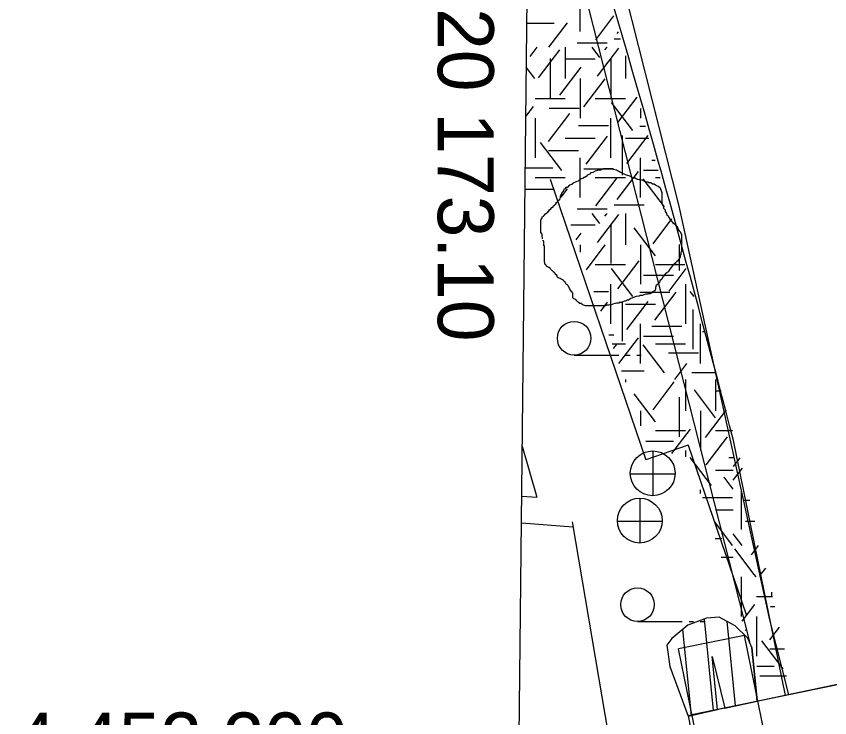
# Model space of a CAD drawing. Extents: x 419677 to 421689, y 4450851 to 4452923.
# Drawn here: x 420150.28 to 420186.6, y 4452201.02 to 4452232.31 of the extents above; entities that cross this region are included whole.
import ezdxf

# ---------------------------------------------------------------- set-up
doc = ezdxf.new("R2010")
doc.units = 0
for name, color, linetype in [('AA_HH', 7, 'Continuous'), ('Level 10', 7, 'Continuous'), ('Level 3', 7, 'Continuous'), ('Level 41', 7, 'Continuous'), ('Level 62', 7, 'Continuous')]:
    doc.layers.add(name, color=color, linetype=linetype)

msp = doc.modelspace()

# ---------------------------------------------------------------- linework, layer by layer
at = {"layer": 'AA_HH'}
for p, q in [((420175.184, 4452217.2), (420177.184, 4452217.2)), ((420177.484, 4452217.2), (420177.684, 4452217.2)), ((420177.984, 4452217.2), (420178.184, 4452217.2)), ((420178.707, 4452210.915), (420178.707, 4452212.915)), ((420177.687, 4452211.905), (420179.687, 4452211.905)), ((420178.13, 4452208.804), (420178.13, 4452210.804)), ((420177.11, 4452209.794), (420179.11, 4452209.794)), ((420178.014, 4452205.314), (420180.014, 4452205.314)), ((420180.314, 4452205.314), (420180.514, 4452205.314)), ((420180.814, 4452205.314), (420181.014, 4452205.314)), ((420180.988, 4452205.421), (420181.393, 4452201.335)), ((420182.003, 4452205.32), (420182.377, 4452201.544)), ((420180.029, 4452204.956), (420180.41, 4452201.119)), ((420183.124, 4452204.147), (420183.362, 4452201.75))]:
    msp.add_line(p, q, dxfattribs=at)
for points in [[(420173.096, 4452234.536), (420705.284, 4452228.915), (420698.004, 4451534.891), (420165.768, 4451540.511)], [(420183.362, 4452201.75), (420183.124, 4452204.147), (420182.934, 4452204.566), (420182.38, 4452205.123), (420181.654, 4452205.502), (420181.097, 4452205.463), (420180.263, 4452205.146), (420179.541, 4452204.558), (420179.324, 4452204.258), (420179.453, 4452203.306), (420180.281, 4452201.091), (420181.59, 4452201.378), (420181.351, 4452203.754), (420181.916, 4452201.447)]]:
    msp.add_lwpolyline(points, close=True, dxfattribs=at)
for points in [[(420174.846, 4452234.518), (420175.212, 4452233.92), (420175.779, 4452232.857), (420179.852, 4452216.802), (420183.01, 4452204.398)], [(420177.158, 4452234.493), (420179.853, 4452223.843), (420183.908, 4452205.378), (420184.76, 4452202.044)], [(420172.87, 4452213.132), (420173.523, 4452210.864)], [(420172.847, 4452210.9), (420173.523, 4452210.864)], [(420210.807, 4452207.509), (420180.279, 4452201.103), (420180.999, 4452197.376), (420210.769, 4452203.894)]]:
    msp.add_lwpolyline(points, dxfattribs=at)
for centre, radius in [((420175.184, 4452217.95), 0.75), ((420178.692, 4452211.923), 1), ((420178.115, 4452209.812), 1), ((420178.014, 4452206.064), 0.75)]:
    msp.add_circle(centre, radius, dxfattribs=at)
at = {"layer": 'Level 10'}
msp.add_line((420172.834, 4452209.708), (420175.136, 4452209.537), dxfattribs=at)
msp.add_lwpolyline([(420175.098, 4452209.758), (420183.741, 4452158.794), (420177.416, 4452142.041), (420172.015, 4452132.085)], dxfattribs=at)
at = {"layer": 'Level 3'}
for points in [[(420176.034, 4452225.364), (420176.138, 4452225.416), (420176.241, 4452225.442), (420176.241, 4452225.468), (420176.267, 4452225.468), (420176.293, 4452225.468), (420176.371, 4452225.468), (420176.501, 4452225.52), (420176.605, 4452225.52), (420176.682, 4452225.52), (420176.734, 4452225.52), (420176.812, 4452225.52), (420176.864, 4452225.52), (420176.89, 4452225.52), (420176.942, 4452225.494), (420177.072, 4452225.468), (420177.253, 4452225.364), (420177.461, 4452225.26), (420177.694, 4452225.182), (420177.772, 4452225.13), (420177.85, 4452225.104), (420177.902, 4452225.104), (420177.954, 4452225.078), (420178.005, 4452225.052), (420178.031, 4452225.052), (420178.083, 4452225.026), (420178.135, 4452225.026), (420178.239, 4452225), (420178.343, 4452224.948), (420178.42, 4452224.922), (420178.472, 4452224.922), (420178.524, 4452224.896), (420178.576, 4452224.896), (420178.602, 4452224.896), (420178.68, 4452224.845), (420178.758, 4452224.845), (420178.81, 4452224.793), (420178.861, 4452224.767), (420178.939, 4452224.741), (420178.991, 4452224.689), (420179.017, 4452224.689), (420179.043, 4452224.611), (420179.043, 4452224.585), (420179.069, 4452224.533), (420179.095, 4452224.455), (420179.095, 4452224.429), (420179.095, 4452224.351), (420179.095, 4452224.299), (420179.095, 4452224.221), (420179.095, 4452224.195), (420179.095, 4452224.117), (420179.095, 4452224.04), (420179.121, 4452223.91), (420179.173, 4452223.832), (420179.173, 4452223.754), (420179.251, 4452223.676), (420179.251, 4452223.598), (420179.302, 4452223.52), (420179.328, 4452223.442), (420179.38, 4452223.416), (420179.406, 4452223.338), (420179.458, 4452223.26), (420179.51, 4452223.183), (420179.588, 4452223.105), (420179.666, 4452223.053), (420179.717, 4452223.001), (420179.743, 4452222.975), (420179.795, 4452222.923), (420179.821, 4452222.819), (420179.873, 4452222.741), (420179.925, 4452222.715), (420179.951, 4452222.637), (420179.951, 4452222.611), (420179.977, 4452222.611), (420179.977, 4452222.585), (420179.977, 4452222.559), (420179.977, 4452222.507), (420179.977, 4452222.404), (420179.977, 4452222.352), (420179.977, 4452222.274), (420179.977, 4452222.196), (420179.977, 4452222.118), (420179.977, 4452222.04), (420179.977, 4452221.962), (420179.977, 4452221.91), (420179.977, 4452221.832), (420179.951, 4452221.78), (420179.951, 4452221.676), (420179.925, 4452221.65), (420179.925, 4452221.573), (420179.899, 4452221.547), (420179.899, 4452221.521), (420179.847, 4452221.469), (420179.795, 4452221.391), (420179.769, 4452221.391), (420179.769, 4452221.365), (420179.743, 4452221.339), (420179.717, 4452221.313), (420179.717, 4452221.287), (420179.692, 4452221.287), (420179.666, 4452221.287)], [(420173.777, 4452222.378), (420173.777, 4452222.404), (420173.777, 4452222.429), (420173.751, 4452222.455), (420173.751, 4452222.481), (420173.751, 4452222.507), (420173.751, 4452222.533), (420173.751, 4452222.559), (420173.751, 4452222.585), (420173.699, 4452222.663), (420173.699, 4452222.741), (420173.699, 4452222.767), (420173.699, 4452222.845), (420173.699, 4452222.923), (420173.699, 4452222.949), (420173.699, 4452222.975), (420173.699, 4452223.001), (420173.699, 4452223.027), (420173.699, 4452223.053), (420173.699, 4452223.079), (420173.699, 4452223.105), (420173.699, 4452223.131), (420173.699, 4452223.157), (420173.699, 4452223.235), (420173.725, 4452223.26), (420173.725, 4452223.286), (420173.725, 4452223.312), (420173.751, 4452223.312), (420173.751, 4452223.338), (420173.751, 4452223.364), (420173.829, 4452223.39), (420173.829, 4452223.416), (420173.907, 4452223.494), (420173.959, 4452223.546), (420174.01, 4452223.572), (420174.01, 4452223.598), (420174.036, 4452223.598), (420174.088, 4452223.676), (420174.14, 4452223.728), (420174.192, 4452223.78), (420174.27, 4452223.832), (420174.27, 4452223.858), (420174.322, 4452223.884), (420174.322, 4452223.91), (420174.348, 4452223.91), (420174.4, 4452223.988), (420174.4, 4452224.014), (420174.477, 4452224.04), (420174.477, 4452224.065), (420174.477, 4452224.091), (420174.529, 4452224.143), (420174.555, 4452224.169), (420174.555, 4452224.195), (420174.581, 4452224.221), (420174.581, 4452224.247), (420174.581, 4452224.273), (420174.581, 4452224.299), (420174.607, 4452224.325), (420174.607, 4452224.351), (420174.607, 4452224.377), (420174.633, 4452224.377), (420174.633, 4452224.403), (420174.633, 4452224.429), (420174.659, 4452224.455), (420174.659, 4452224.481), (420174.711, 4452224.507), (420174.737, 4452224.585), (420174.737, 4452224.611), (420174.815, 4452224.637), (420174.815, 4452224.663), (420174.815, 4452224.689), (420174.892, 4452224.689), (420174.944, 4452224.741), (420174.944, 4452224.767), (420174.97, 4452224.767), (420174.996, 4452224.793), (420175.074, 4452224.819), (420175.1, 4452224.845), (420175.126, 4452224.845), (420175.126, 4452224.871), (420175.178, 4452224.896), (420175.282, 4452224.922), (420175.282, 4452224.948), (420175.385, 4452224.974), (420175.437, 4452225.026), (420175.463, 4452225.026), (420175.463, 4452225.052), (420175.463, 4452225.078), (420175.515, 4452225.078), (420175.619, 4452225.104), (420175.619, 4452225.13), (420175.645, 4452225.13), (420175.671, 4452225.13), (420175.671, 4452225.156), (420175.723, 4452225.182), (420175.749, 4452225.182), (420175.8, 4452225.234), (420175.878, 4452225.286), (420175.93, 4452225.312), (420175.93, 4452225.338), (420176.034, 4452225.364)], [(420175.723, 4452219.391), (420175.697, 4452219.391), (420175.567, 4452219.443), (420175.541, 4452219.469), (420175.515, 4452219.469), (420175.515, 4452219.495), (420175.437, 4452219.495), (420175.385, 4452219.547), (420175.308, 4452219.625), (420175.256, 4452219.677), (420175.178, 4452219.703), (420175.152, 4452219.729), (420175.126, 4452219.755), (420175.126, 4452219.781), (420175.126, 4452219.859), (420175.126, 4452219.937), (420175.126, 4452219.962), (420175.1, 4452219.988), (420175.1, 4452220.014), (420175.074, 4452220.014), (420175.022, 4452220.092), (420174.97, 4452220.17), (420174.944, 4452220.248), (420174.918, 4452220.274), (420174.918, 4452220.3), (420174.892, 4452220.326), (420174.841, 4452220.352), (420174.815, 4452220.378), (420174.815, 4452220.404), (420174.789, 4452220.43), (420174.789, 4452220.456), (420174.711, 4452220.508), (420174.711, 4452220.534), (420174.685, 4452220.56), (420174.607, 4452220.586), (420174.555, 4452220.612), (420174.477, 4452220.638), (420174.451, 4452220.664), (420174.426, 4452220.69), (420174.426, 4452220.716), (420174.426, 4452220.742), (420174.348, 4452220.793), (420174.348, 4452220.819), (420174.322, 4452220.845), (420174.322, 4452220.871), (420174.296, 4452220.871), (420174.296, 4452220.897), (420174.27, 4452220.897), (420174.244, 4452220.923), (420174.218, 4452220.949), (420174.192, 4452220.975), (420174.166, 4452221.001), (420174.14, 4452221.027), (420174.114, 4452221.053), (420174.114, 4452221.079), (420174.062, 4452221.105), (420174.036, 4452221.105), (420174.01, 4452221.131), (420173.959, 4452221.157), (420173.933, 4452221.183), (420173.933, 4452221.209), (420173.907, 4452221.235), (420173.881, 4452221.261), (420173.881, 4452221.287), (420173.881, 4452221.313), (420173.855, 4452221.339), (420173.855, 4452221.365), (420173.855, 4452221.391), (420173.855, 4452221.469), (420173.855, 4452221.521), (420173.855, 4452221.547), (420173.855, 4452221.573), (420173.855, 4452221.598), (420173.855, 4452221.624), (420173.855, 4452221.65), (420173.855, 4452221.676), (420173.855, 4452221.702), (420173.855, 4452221.728), (420173.855, 4452221.754), (420173.855, 4452221.78), (420173.855, 4452221.806), (420173.855, 4452221.832), (420173.855, 4452221.858), (420173.855, 4452221.884), (420173.855, 4452221.91), (420173.855, 4452221.936), (420173.855, 4452222.014), (420173.855, 4452222.04), (420173.855, 4452222.066), (420173.829, 4452222.066), (420173.829, 4452222.092), (420173.829, 4452222.118), (420173.829, 4452222.144), (420173.829, 4452222.17), (420173.829, 4452222.196), (420173.829, 4452222.222), (420173.829, 4452222.248), (420173.829, 4452222.274), (420173.803, 4452222.274), (420173.803, 4452222.3), (420173.803, 4452222.326)], [(420179.666, 4452221.287), (420179.614, 4452221.235), (420179.458, 4452221.027), (420179.406, 4452220.949), (420179.38, 4452220.897), (420179.354, 4452220.897), (420179.328, 4452220.871), (420179.302, 4452220.871), (420179.302, 4452220.845), (420179.276, 4452220.845), (420179.276, 4452220.819), (420179.251, 4452220.819), (420179.251, 4452220.793), (420179.225, 4452220.793), (420179.199, 4452220.716), (420179.173, 4452220.716), (420179.147, 4452220.69), (420179.095, 4452220.586), (420179.017, 4452220.508), (420178.991, 4452220.43), (420178.913, 4452220.352), (420178.887, 4452220.352), (420178.861, 4452220.326), (420178.861, 4452220.3), (420178.835, 4452220.3), (420178.835, 4452220.274), (420178.81, 4452220.196), (420178.81, 4452220.144), (420178.784, 4452220.066), (420178.706, 4452220.04), (420178.706, 4452220.014), (420178.68, 4452220.014), (420178.68, 4452219.988), (420178.654, 4452219.988), (420178.654, 4452219.962), (420178.628, 4452219.962), (420178.602, 4452219.962), (420178.576, 4452219.937), (420178.55, 4452219.937), (420178.524, 4452219.937), (420178.498, 4452219.937), (420178.472, 4452219.911), (420178.446, 4452219.911), (420178.42, 4452219.911), (420178.394, 4452219.911), (420178.369, 4452219.911), (420178.291, 4452219.885), (420178.239, 4452219.859), (420178.161, 4452219.859), (420178.135, 4452219.859), (420178.083, 4452219.833), (420177.954, 4452219.807), (420177.72, 4452219.729), (420177.616, 4452219.651), (420177.538, 4452219.651), (420177.513, 4452219.625), (420177.487, 4452219.625), (420177.461, 4452219.599), (420177.435, 4452219.599), (420177.357, 4452219.573), (420177.305, 4452219.547), (420177.279, 4452219.547), (420177.253, 4452219.547), (420177.227, 4452219.547), (420177.201, 4452219.547), (420177.201, 4452219.521), (420177.175, 4452219.521), (420177.149, 4452219.521), (420177.072, 4452219.521), (420177.02, 4452219.495), (420176.916, 4452219.469), (420176.838, 4452219.443), (420176.734, 4452219.417), (420176.682, 4452219.417), (420176.656, 4452219.417), (420176.631, 4452219.417), (420176.605, 4452219.417), (420176.605, 4452219.391), (420176.579, 4452219.391), (420176.553, 4452219.391), (420176.527, 4452219.391), (420176.501, 4452219.391), (420176.475, 4452219.391), (420176.449, 4452219.391), (420176.423, 4452219.391), (420176.397, 4452219.391), (420176.371, 4452219.391), (420176.293, 4452219.391), (420176.241, 4452219.391), (420176.164, 4452219.391), (420176.112, 4452219.391), (420176.086, 4452219.391), (420176.06, 4452219.391), (420176.008, 4452219.391), (420175.93, 4452219.391), (420175.904, 4452219.391), (420175.852, 4452219.391), (420175.826, 4452219.391), (420175.774, 4452219.391), (420175.749, 4452219.391), (420175.723, 4452219.391)]]:
    msp.add_lwpolyline(points, dxfattribs=at)
at = {"layer": 'Level 41'}
for p, q in [((420175.459, 4452231.638), (420175.459, 4452233.406)), ((420176.149, 4452231.262), (420176.963, 4452232.333)), ((420173.07, 4452232.011), (420174.292, 4452232.011)), ((420174.058, 4452230.929), (420174.887, 4452232.02)), ((420177.109, 4452231.541), (420177.167, 4452231.618)), ((420176.972, 4452231.31), (420177.255, 4452231.31)), ((420173.221, 4452230.512), (420173.538, 4452230.929)), ((420174.787, 4452230.929), (420174.787, 4452229.531)), ((420175.32, 4452231.135), (420176.663, 4452231.135)), ((420176.336, 4452230.477), (420175.992, 4452230.929)), ((420176.229, 4452229.635), (420177.179, 4452230.885)), ((420176.562, 4452230.809), (420176.653, 4452230.929)), ((420173.592, 4452229.566), (420174.541, 4452230.816)), ((420177.473, 4452230.549), (420177.473, 4452229.531)), ((420174.112, 4452230.427), (420174.112, 4452228.66)), ((420174.787, 4452230.415), (420176.13, 4452230.415)), ((420176.829, 4452230.462), (420176.829, 4452228.695)), ((420173.432, 4452229.531), (420173.049, 4452230.036)), ((420174.552, 4452228.794), (420175.501, 4452230.044)), ((420175.459, 4452229.531), (420175.459, 4452227.764)), ((420175.618, 4452228.269), (420176.567, 4452229.519)), ((420177.135, 4452227.568), (420178, 4452228.704)), ((420173.444, 4452228.647), (420174.787, 4452228.647)), ((420176.13, 4452228.647), (420177.473, 4452228.647)), ((420177.801, 4452227.218), (420176.851, 4452228.467)), ((420173.026, 4452227.839), (420173.37, 4452228.292)), ((420174.046, 4452226.726), (420174.995, 4452227.976)), ((420174.068, 4452228.213), (420175.411, 4452228.213)), ((420178.145, 4452228.197), (420178.145, 4452227.764)), ((420173.444, 4452227.764), (420173.444, 4452225.997)), ((420176.802, 4452227.764), (420176.802, 4452225.997)), ((420175.374, 4452227.44), (420176.717, 4452227.44)), ((420178.116, 4452227.407), (420178.371, 4452227.407)), ((420174.787, 4452226.88), (420176.13, 4452226.88)), ((420175.723, 4452225.71), (420176.673, 4452226.96)), ((420177.334, 4452226.992), (420177.334, 4452225.224)), ((420177.473, 4452226.88), (420178.521, 4452226.88)), ((420177.534, 4452225.746), (420178.483, 4452226.995)), ((420174.631, 4452225.429), (420173.682, 4452226.679)), ((420174.041, 4452226.32), (420175.384, 4452226.32)), ((420175.459, 4452224.229), (420175.459, 4452225.997)), ((420178.145, 4452224.229), (420178.145, 4452225.997)), ((420178.65, 4452225.899), (420178.802, 4452225.899)), ((420173.001, 4452225.548), (420174.239, 4452225.548)), ((420175.613, 4452225.514), (420176.956, 4452225.514)), ((420178.276, 4452225.443), (420178.932, 4452225.443)), ((420173.444, 4452225.113), (420174.787, 4452225.113)), ((420176.13, 4452225.113), (420177.473, 4452225.113)), ((420176.149, 4452223.853), (420177.098, 4452225.102)), ((420177.109, 4452224.132), (420178.058, 4452225.382)), ((420179.212, 4452223.818), (420178.262, 4452225.067)), ((420178.816, 4452225.113), (420179.026, 4452225.113)), ((420172.991, 4452224.602), (420174.292, 4452224.602)), ((420174.608, 4452224.243), (420174.887, 4452224.611)), ((420175.32, 4452223.726), (420176.663, 4452223.726)), ((420176.972, 4452223.901), (420178.315, 4452223.901)), ((420176.336, 4452223.068), (420175.992, 4452223.52)), ((420176.229, 4452222.226), (420177.179, 4452223.476)), ((420176.562, 4452223.4), (420176.653, 4452223.52)), ((420177.473, 4452223.52), (420177.473, 4452222.122)), ((420178.706, 4452222.157), (420179.552, 4452223.272)), ((420175.037, 4452223.006), (420176.13, 4452223.006)), ((420176.829, 4452223.053), (420176.829, 4452221.286)), ((420178.813, 4452221.631), (420177.864, 4452222.88)), ((420175.271, 4452222.332), (420175.501, 4452222.635)), ((420175.459, 4452222.122), (420175.459, 4452221.79)), ((420175.73, 4452221.008), (420176.567, 4452222.11)), ((420178.145, 4452222.122), (420178.145, 4452220.355)), ((420179.877, 4452222.135), (420179.877, 4452220.965)), ((420176.13, 4452221.238), (420177.473, 4452221.238)), ((420177.135, 4452220.159), (420178.086, 4452221.408)), ((420178.816, 4452221.238), (420180.133, 4452221.238)), ((420177.801, 4452219.809), (420176.851, 4452221.058)), ((420178.276, 4452220.768), (420179.619, 4452220.768)), ((420179.426, 4452220.054), (420180.186, 4452221.055)), ((420176.802, 4452220.355), (420176.802, 4452218.588)), ((420180.159, 4452220.355), (420180.159, 4452218.588)), ((420176.069, 4452220.031), (420176.717, 4452220.031)), ((420178.116, 4452219.998), (420179.459, 4452219.998)), ((420178.786, 4452218.757), (420179.736, 4452220.007)), ((420180.541, 4452219.811), (420180.367, 4452220.04)), ((420176.373, 4452219.156), (420176.673, 4452219.551)), ((420177.334, 4452219.583), (420177.334, 4452217.815)), ((420177.473, 4452219.471), (420178.816, 4452219.471)), ((420177.534, 4452218.337), (420178.483, 4452219.586)), ((420180.477, 4452219.233), (420180.477, 4452217.465)), ((420178.145, 4452216.82), (420178.145, 4452218.588)), ((420180.831, 4452216.82), (420180.831, 4452218.588)), ((420178.65, 4452218.49), (420179.993, 4452218.49)), ((420180.913, 4452218.245), (420180.989, 4452218.245)), ((420176.738, 4452218.105), (420176.956, 4452218.105)), ((420177.183, 4452216.821), (420178.058, 4452217.973)), ((420178.276, 4452218.034), (420179.619, 4452218.034)), ((420176.877, 4452217.704), (420177.473, 4452217.704)), ((420176.949, 4452217.496), (420177.098, 4452217.693)), ((420179.212, 4452216.409), (420178.262, 4452217.658)), ((420178.816, 4452217.704), (420180.159, 4452217.704)), ((420179.395, 4452217.297), (420180.738, 4452217.297)), ((420179.678, 4452216.111), (420180.215, 4452216.817)), ((420177.297, 4452216.492), (420178.315, 4452216.492)), ((420180.434, 4452216.423), (420181.509, 4452216.423)), ((420177.473, 4452216.111), (420177.473, 4452215.985)), ((420178.706, 4452214.748), (420179.655, 4452215.998)), ((420180.159, 4452216.111), (420180.159, 4452214.713)), ((420181.502, 4452216.111), (420181.502, 4452214.713)), ((420181.502, 4452216.111), (420181.502, 4452214.713)), ((420181.503, 4452214.397), (420180.554, 4452215.646)), ((420178.813, 4452214.222), (420177.864, 4452215.471)), ((420179.877, 4452215.323), (420179.877, 4452213.556)), ((420181.502, 4452215.597), (420181.745, 4452215.597)), ((420178.145, 4452214.713), (420178.145, 4452214.048)), ((420180.831, 4452214.713), (420180.831, 4452212.946)), ((420180.831, 4452214.713), (420180.831, 4452212.946)), ((420181.051, 4452213.52), (420181.987, 4452214.752)), ((420178.816, 4452213.829), (420180.159, 4452213.829)), ((420179.553, 4452212.812), (420180.375, 4452213.895)), ((420181.502, 4452213.829), (420182.25, 4452213.829)), ((420181.077, 4452212.294), (420182.027, 4452213.543)), ((420178.384, 4452213.359), (420179.619, 4452213.359)), ((420180.159, 4452212.946), (420180.159, 4452212.661)), ((420181.316, 4452211.382), (420180.367, 4452212.631)), ((420182.086, 4452212.622), (420182.29, 4452212.622)), ((420182.3, 4452212.225), (420182.597, 4452212.616)), ((420181.502, 4452212.062), (420182.29, 4452212.062)), ((420182.29, 4452211.616), (420182.703, 4452212.159)), ((420182.29, 4452211.222), (420181.884, 4452211.756)), ((420180.831, 4452211.02), (420180.831, 4452211.179)), ((420182.652, 4452209.411), (420182.652, 4452211.179)), ((420180.913, 4452210.836), (420182.256, 4452210.836)), ((420182.775, 4452210.73), (420183.035, 4452210.73)), ((420181.502, 4452210.295), (420182.29, 4452210.295)), ((420182.261, 4452208.702), (420181.459, 4452209.758)), ((420182.829, 4452209.784), (420183.255, 4452209.784)), ((420182.684, 4452208.702), (420182.29, 4452209.22)), ((420181.484, 4452209.014), (420181.777, 4452209.014)), ((420183.227, 4452207.415), (420182.362, 4452208.554)), ((420183.1, 4452208.285), (420183.417, 4452208.702)), ((420181.753, 4452208.188), (420182.29, 4452208.188)), ((420183.496, 4452207.372), (420183.741, 4452207.694)), ((420182.652, 4452205.537), (420182.652, 4452207.304)), ((420183.311, 4452207.304), (420183.227, 4452207.415)), ((420183.471, 4452207.339), (420183.496, 4452207.372)), ((420183.991, 4452206.619), (420183.991, 4452206.433)), ((420183.323, 4452206.42), (420184.037, 4452206.42)), ((420182.686, 4452205.324), (420183.249, 4452206.065)), ((420183.947, 4452205.986), (420184.138, 4452205.986)), ((420183.323, 4452205.537), (420183.323, 4452203.77)), ((420182.821, 4452204.907), (420182.849, 4452204.943)), ((420183.925, 4452204.499), (420184.353, 4452205.063)), ((420184.51, 4452203.202), (420183.561, 4452204.452)), ((420183.92, 4452204.093), (420184.578, 4452204.093)), ((420183.338, 4452203.321), (420184.118, 4452203.321)), ((420183.479, 4452202.886), (420184.666, 4452202.886))]:
    msp.add_line(p, q, dxfattribs=at)
at = {"layer": 'Level 62'}
for p, q in [((420174.113, 4452225.053), (420178.389, 4452212.531)), ((420180.282, 4452213.177), (420178.389, 4452212.531)), ((420180.282, 4452213.177), (420182.864, 4452205.618)), ((420184.624, 4452202.006), (420182.295, 4452213.388)), ((420223.133, 4452209.884), (420180.445, 4452201.151)), ((420182.784, 4452204.693), (420179.844, 4452204.091)), ((420182.784, 4452204.693), (420179.844, 4452204.091)), ((420182.784, 4452204.693), (420179.844, 4452204.091)), ((420184.738, 4452195.141), (420182.784, 4452204.693)), ((420184.738, 4452195.141), (420182.784, 4452204.693)), ((420184.738, 4452195.141), (420182.784, 4452204.693)), ((420181.798, 4452194.539), (420179.844, 4452204.091)), ((420181.798, 4452194.539), (420179.844, 4452204.091)), ((420181.798, 4452194.539), (420179.844, 4452204.091))]:
    msp.add_line(p, q, dxfattribs=at)
msp.add_arc((419652.958, 4452077.572), 546.483, 14.39038, 16.68809, dxfattribs=at)

# ---------------------------------------------------------------- texts
at = {"layer": 'AA_HH'}
msp.add_text('420 173.10', height=2.5, rotation=270, dxfattribs=at).set_placement((420169.096, 4452234.536))
msp.add_text('4 452 200', height=2.5, dxfattribs=at).set_placement((420150.2, 4452198.75))

doc.saveas('drawing.dxf')
